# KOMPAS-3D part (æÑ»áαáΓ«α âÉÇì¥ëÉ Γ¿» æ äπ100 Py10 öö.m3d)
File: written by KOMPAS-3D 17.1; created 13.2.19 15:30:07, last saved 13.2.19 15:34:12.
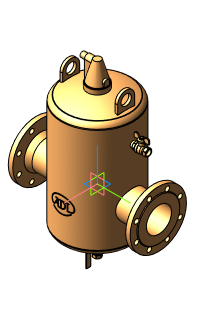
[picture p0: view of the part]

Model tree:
1. Операция без истории:5  (labels: Сталь 20  ГОСТ 1050-2013)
